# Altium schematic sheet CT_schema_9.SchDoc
size 387 x 278 mm
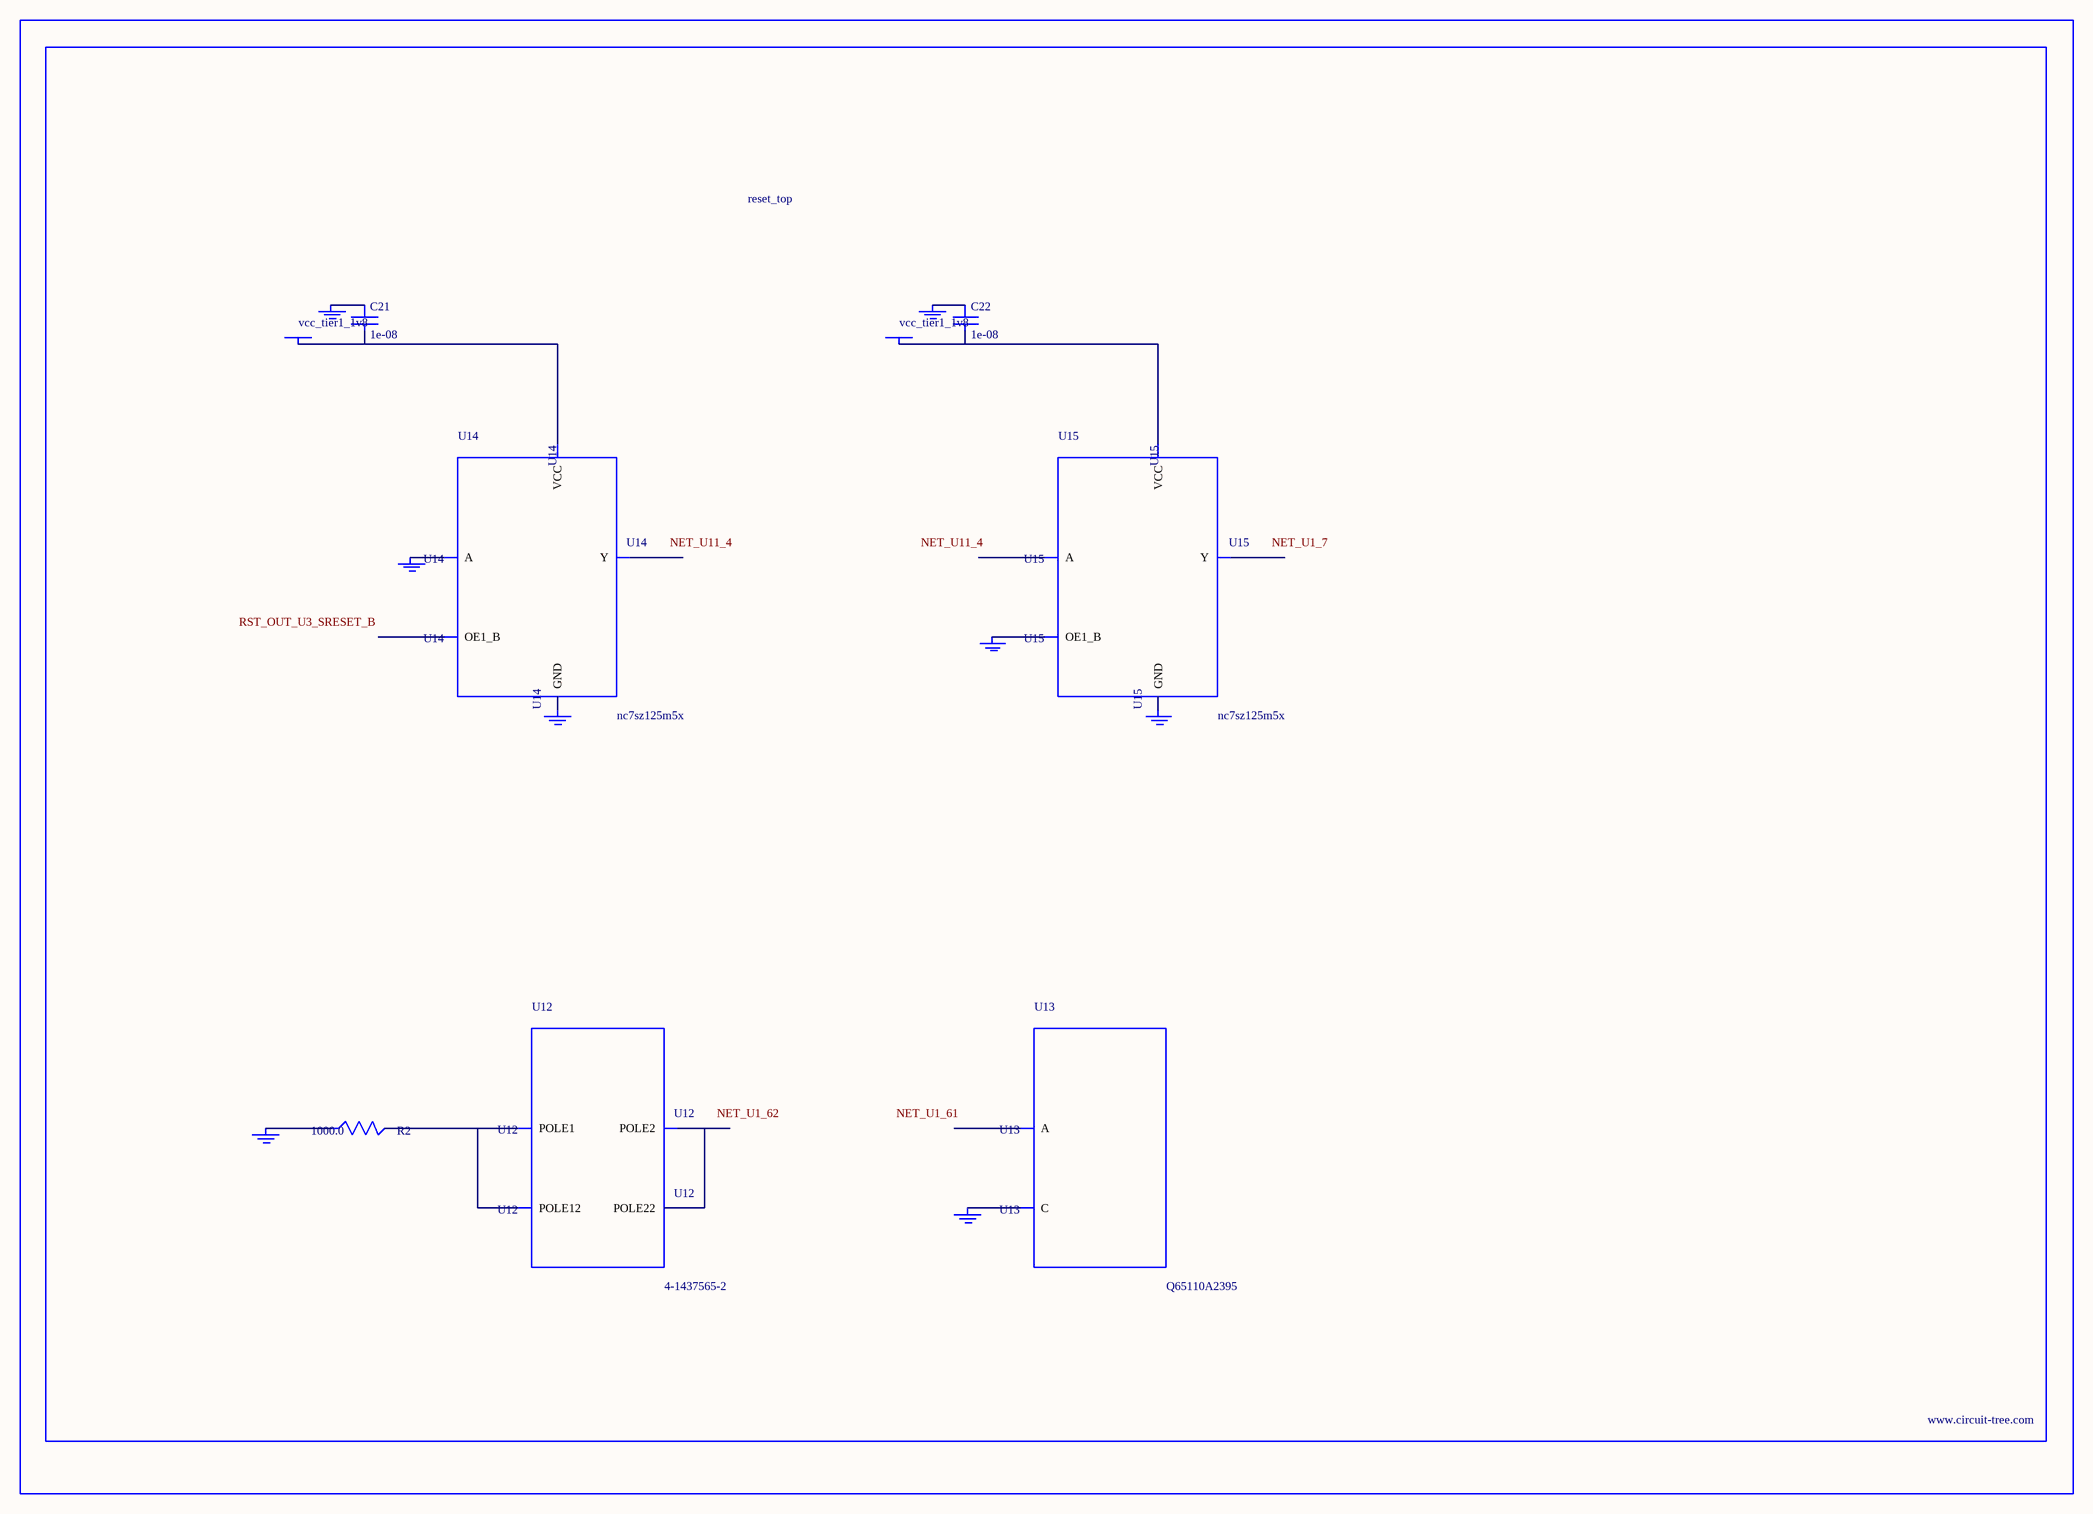
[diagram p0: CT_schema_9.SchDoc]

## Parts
BORDER8  (no value)
C21  1e-08  [C0402]
C22  1e-08  [C0402]
GND_INSTANCE_8_0  (no value)
GND_INSTANCE_8_1  (no value)
GND_INSTANCE_8_2  (no value)
GND_INSTANCE_8_3  (no value)
GND_INSTANCE_8_4  (no value)
GND_INSTANCE_8_5  (no value)
GND_INSTANCE_8_6  (no value)
GND_INSTANCE_8_7  (no value)
POWER_INSTANCE_8_0  vcc_tier1_1v8
POWER_INSTANCE_8_1  vcc_tier1_1v8
R2  1000.0  [R0603]
U12  4-1437565-2  [SW_4-1437565-2]
U13  Q65110A2395  [LGM67K-G1J2-24-Z]
U14  nc7sz125m5x  [NC7SZ125M5X]
U15  nc7sz125m5x  [NC7SZ125M5X]

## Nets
NetC21_1: C21.1 GND_INSTANCE_8_2.0(GND)
NetC21_2: C21.2 POWER_INSTANCE_8_0.0(PWR) U14.5(VCC)
NetC22_1: C22.1 GND_INSTANCE_8_5.0(GND)
NetC22_2: C22.2 POWER_INSTANCE_8_1.0(PWR) U15.5(VCC)
NetGND_INSTANCE_8_0_0: GND_INSTANCE_8_0.0(GND) R2.1
NetGND_INSTANCE_8_1_0: GND_INSTANCE_8_1.0(GND) U13.C
NetGND_INSTANCE_8_3_0: GND_INSTANCE_8_3.0(GND) U14.2(A)
NetGND_INSTANCE_8_4_0: GND_INSTANCE_8_4.0(GND) U14.3(GND)
NetGND_INSTANCE_8_6_0: GND_INSTANCE_8_6.0(GND) U15.1(OE1_B)
NetGND_INSTANCE_8_7_0: GND_INSTANCE_8_7.0(GND) U15.3(GND)
NetR2_2: R2.2 U12.1(POLE1) U12.2(POLE12)
NetU12_3: U12.3(POLE2) U12.4(POLE22)

Not connected (* = marked no-connect by the designer): U13 A; U14 1(OE1_B) 4(Y); U15 2(A) 4(Y)

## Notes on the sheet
- Labels drawn without touching a wire or pin: NET_U1_7, NET_U1_61, NET_U1_62, NET_U11_4, RST_OUT_U3_SRESET_B

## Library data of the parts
BORDER8 = BORDER_PAGE8
C21 C22 = C0402C103K3RAC
GND_INSTANCE_8_0-GND_INSTANCE_8_7 = GND
POWER_INSTANCE_8_0 POWER_INSTANCE_8_1 = PWR
R2 = RC0603JR-071KL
